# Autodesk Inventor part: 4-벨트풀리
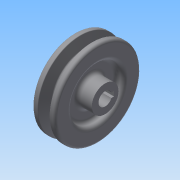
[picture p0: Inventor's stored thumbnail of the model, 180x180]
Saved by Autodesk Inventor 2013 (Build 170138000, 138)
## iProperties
Created: 2015-02
Part Number: 4-벨트풀리
Material: 일반
Document SubType Name: Modeling
Designer: Administrator
Density: 1 g/cm^3
Author: Administrator
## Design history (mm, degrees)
sketch "스케치1"
  geometry: L1 (0, 0)-(25, 0); L2 (0, 0)-(0, 11); L3 (0, 11)-(6, 11); L4 (6, 11)-(6, 21.5); L5 (6, 21.5)-(0, 21.5); L6 (0, 21.5)-(0, 35.2); L7 (0, 35.2)-(4.675, 35.2); L8 (4.675, 35.2)-(7.426, 26.2); L9 (7.426, 26.2)-(11.574, 26.2); L10 (11.574, 26.2)-(14.325, 35.2); L11 (14.325, 35.2)-(19, 35.2); L12 (19, 35.2)-(19, 21.5); L13 (19, 21.5)-(13, 21.5); L14 (13, 21.5)-(13, 11); L15 (13, 11)-(25, 11); L16 (25, 11)-(25, 0); 2 further points
  constraints: 32 end point, 9 parallel, 6 collinear, 3 equal length, 2 perpendicular, 2 point on line, 1 horizontal, 1 horizontal alignment
  dimensions: "d0" = 25 distance of L1.start L1.end; "d1" = 43 diameter of L5 L1; "d2" = 6 distance of L2.end L3.end; "d3" = 19 distance between parallel lines of L12 L6; "d4" = 34 deg angle of L10 L8; "d5" = 2.7 distance from line of point (5.5, 32.5) L7; "d6" = 6.3 distance from line of L9 point (5.5, 32.5); "d7" = 8 distance of point (13.5, 32.5) point (5.5, 32.5); "d8" = 22 diameter of L15 L1; "d9" = 65 diameter of point (5.5, 32.5) L1
revolve "회전1" sketch "스케치1" stored, may be unused: angle "d10" = 90 deg
sketch "스케치2"
  geometry: L1 (-2, 5.123)-(-2, 7.3); L2 (-2, 7.3)-(2, 7.3); L3 (2, 7.3)-(2, 5.123); C1 r 11 at (0, 0) reference; A1 r 5.5 centre (0, 0) between (-2, 5.123) and (2, 5.123); 1 further point
  constraints: 6 end point, 2 point on circle, 1 centre point, 1 coincident, 1 midpoint, 1 parallel, 1 perpendicular, 1 vertical, 1 vertical alignment
  dimensions: "d11" = 4 distance of L1.end L2.end; "d13" = 12.8 dimension on A1 L2; "d14" = 11 diameter of A1
extrude "돌출1" cut sketch "스케치2" stored distance "d15" = 10; taper "d16" = 0 deg
fillet "모깎기1" dims "d17" = 2, "d18" = 0.5, "d19" = 1, "d20" = 3
node "솔리드1"
